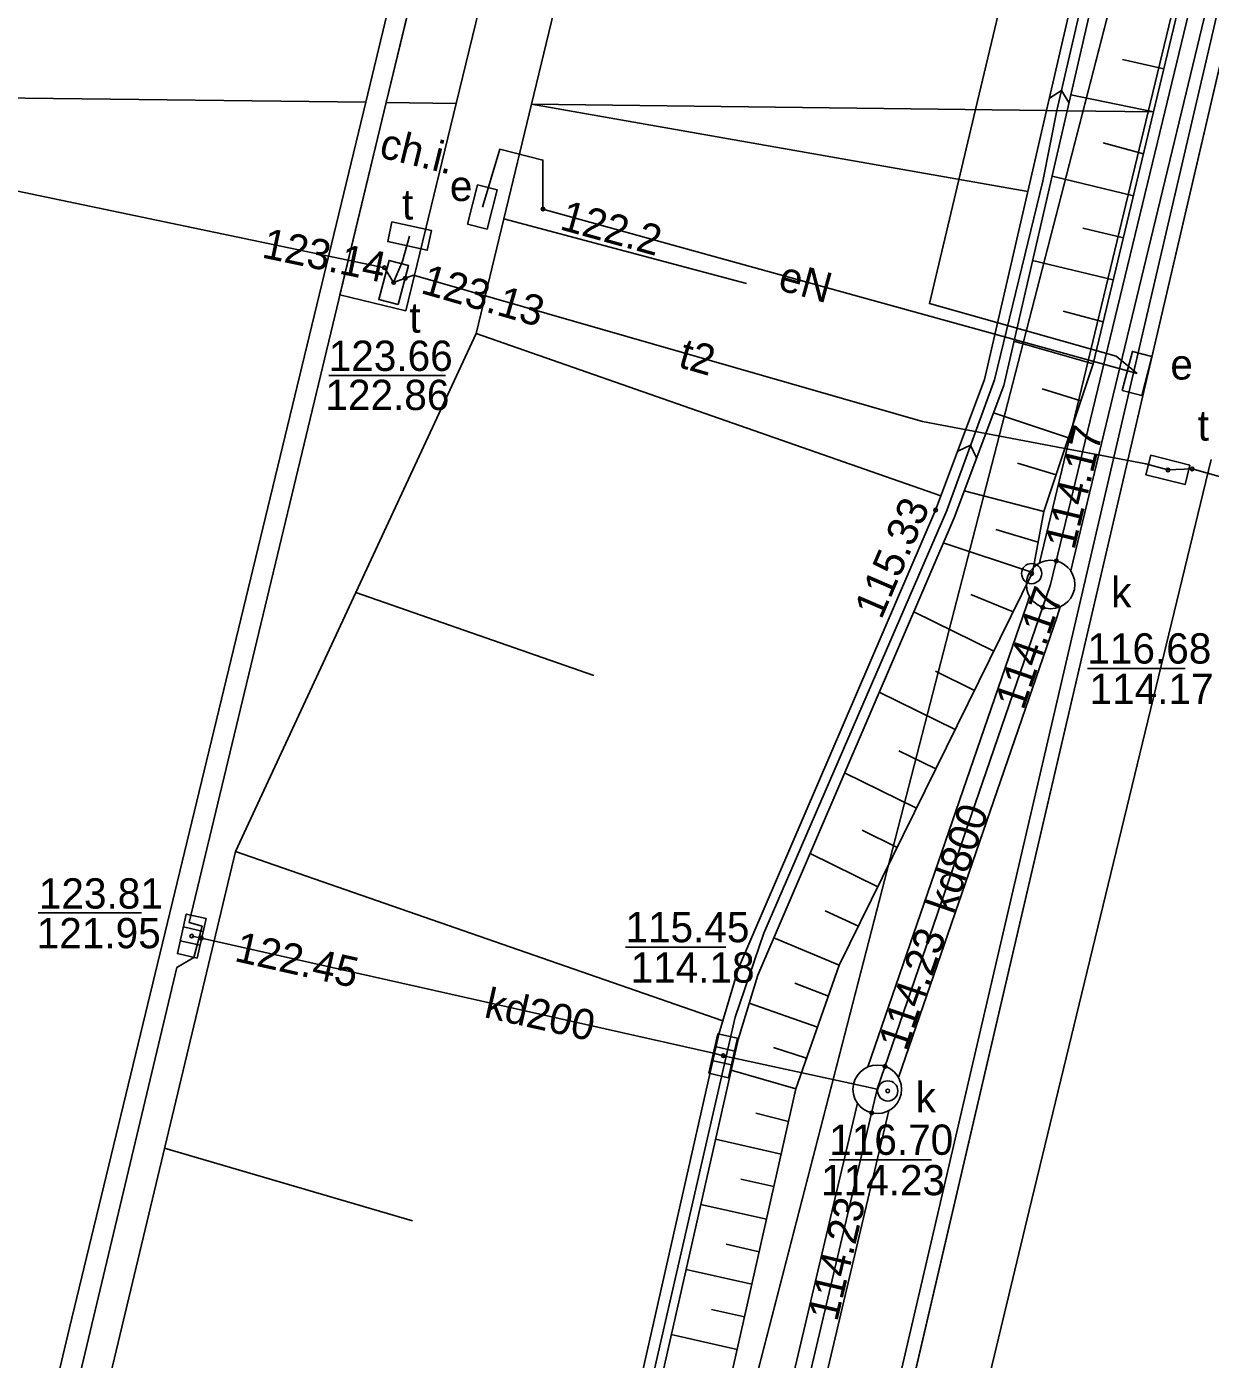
# Model space of a CAD drawing. Extents: x 6424617 to 6425697, y 5665845 to 5667190.
# Drawn here: x 6425313.55 to 6425342.83, y 5666283.39 to 5666316.36 of the extents above; entities that cross this region are included whole.
import ezdxf

# ---------------------------------------------------------------- set-up
doc = ezdxf.new("R2010")
doc.units = 0
for name, color, linetype in [('Warstwa 1', 7, 'Continuous'), ('Warstwa 12', 7, 'Continuous'), ('Warstwa 13', 7, 'Continuous'), ('Warstwa 14', 7, 'Continuous'), ('Warstwa 15', 7, 'Continuous'), ('Warstwa 16', 7, 'Continuous'), ('Warstwa 2', 7, 'Continuous'), ('Warstwa 20', 7, 'Continuous'), ('Warstwa 21', 7, 'Continuous'), ('Warstwa 25', 7, 'Continuous'), ('Warstwa 4', 7, 'Continuous'), ('Warstwa 5', 7, 'Continuous'), ('Warstwa 6', 7, 'Continuous'), ('Warstwa 61', 7, 'Continuous'), ('Warstwa 8', 7, 'Continuous'), ('Warstwa 9', 7, 'Continuous')]:
    doc.layers.add(name, color=color, linetype=linetype)

msp = doc.modelspace()

# ---------------------------------------------------------------- linework, layer by layer
at = {"layer": 'Warstwa 1'}
for p, q in [((6425328.388, 5666270.5), (6425353.441, 5666367.596)), ((6425328.388, 5666270.5), (6425353.441, 5666367.596)), ((6425325.89, 5666241.74), (6425352.06, 5666353.98)), ((6425325.89, 5666241.74), (6425352.06, 5666353.98))]:
    msp.add_line(p, q, dxfattribs=at)
at = {"layer": 'Warstwa 12'}
for points in [[(6425398.761, 5666563.583), (6425397.55, 5666559.5), (6425397.03, 5666557.16), (6425392.45, 5666536.96), (6425386, 5666508.09), (6425382.01, 5666490.27), (6425381.21, 5666479.99), (6425379.9, 5666475.3), (6425381.52, 5666474.89), (6425375.93, 5666454.14), (6425373.99, 5666454.38), (6425373.44, 5666451.82), (6425375.23, 5666451.4), (6425362.43, 5666401.17), (6425355.8, 5666402.66), (6425355.08, 5666402.04), (6425351.66, 5666389.66), (6425350.42, 5666384.46), (6425347.89, 5666373.29), (6425344.69, 5666359.22), (6425346.02, 5666355.28), (6425340.77, 5666330.04), (6425337.023, 5666314.31)], [(6425341.293, 5666314.258), (6425351.556, 5666356.819)], [(6425352.334, 5666356.631), (6425342.114, 5666314.249)], [(6425337.023, 5666314.31), (6425335.88, 5666309.51), (6425340.5, 5666308.21), (6425341.02, 5666307.78)], [(6425338.604, 5666303.093), (6425341.293, 5666314.258)], [(6425342.114, 5666314.249), (6425339.438, 5666303.145), (6425339.376, 5666302.897)], [(6425358.838, 5666300.979), (6425358.436, 5666301.076), (6425355.839, 5666301.623), (6425342.381, 5666305.421), (6425341.781, 5666305.394), (6425341.237, 5666305.542), (6425335.71, 5666306.592), (6425323.113, 5666310.211), (6425322.626, 5666310.032), (6425322.397, 5666310.399), (6425305.47, 5666313.931)], [(6425341.02, 5666307.78), (6425326.32, 5666311.85), (6425326.32, 5666313.06), (6425325.25, 5666313.33), (6425324.82, 5666311.9)], [(6425322.626, 5666310.032), (6425322.848, 5666310.561), (6425323.02, 5666311.182)], [(6425334.359, 5666290.624), (6425334.442, 5666290.861), (6425338.281, 5666302.028), (6425338.359, 5666302.262)], [(6425339.118, 5666302.009), (6425339.039, 5666301.772), (6425335.116, 5666290.359)], [(6425334.59, 5666290.07), (6425333.91, 5666290.22), (6425331.02, 5666290.85), (6425330.78, 5666290.9), (6425330.54, 5666290.96), (6425317.87, 5666293.81), (6425317.63, 5666293.86)], [(6425320.019, 5666230.08), (6425320.081, 5666230.334), (6425334.098, 5666289.726)], [(6425334.876, 5666289.542), (6425320.859, 5666230.146), (6425320.795, 5666229.889)]]:
    msp.add_lwpolyline(points, dxfattribs=at)
at = {"layer": 'Warstwa 14'}
for p, q in [((6425323.909, 5666307.735), (6425321.022, 5666307.735)), ((6425339.79, 5666300.478), (6425342.208, 5666300.478)), ((6425316.386, 5666294.435), (6425313.829, 5666294.435)), ((6425330.843, 5666293.585), (6425328.364, 5666293.585)), ((6425333.4, 5666288.323), (6425335.936, 5666288.323))]:
    msp.add_line(p, q, dxfattribs=at)
for centre in [(6425326.32, 5666311.85), (6425322.397, 5666310.399), (6425322.627, 5666310.032), (6425322.913, 5666310.138), (6425341.781, 5666305.394), (6425342.381, 5666305.421), (6425339.021, 5666303.143), (6425338.41, 5666302.83), (6425338.685, 5666301.993), (6425317.63, 5666293.86), (6425317.87, 5666293.81), (6425330.78, 5666290.9), (6425334.785, 5666290.637), (6425334.85, 5666290.03), (6425334.452, 5666289.486)]:
    msp.add_circle(centre, 0.045, dxfattribs=at)
at = {"layer": 'Warstwa 16'}
for centre in [(6425338.88, 5666302.56), (6425334.59, 5666290.07)]:
    msp.add_circle(centre, 0.6, dxfattribs=at)
at = {"layer": 'Warstwa 2'}
for points in [[(6425342.431, 5666314.245), (6425342.9, 5666316.26), (6425351.432, 5666353.898), (6425342.677, 5666355.997), (6425354.705, 5666404.396), (6425364.488, 5666402.728), (6425382.828, 5666478.302), (6425401.605, 5666563.549)], [(6425303.473, 5666148.344), (6425306.362, 5666159.088), (6425314.292, 5666194.437), (6425325.907, 5666243.233), (6425342.431, 5666314.245)]]:
    msp.add_lwpolyline(points, dxfattribs=at)
at = {"layer": 'Warstwa 20'}
for points in [[(6425326.04, 5666314.442), (6425336.507, 5666357.769), (6425337.041, 5666371.794), (6425341.788, 5666390.934), (6425346.79, 5666410.35), (6425362.358, 5666467.618), (6425366.796, 5666476.821), (6425368.004, 5666481.671), (6425368.42, 5666492.007), (6425372.53, 5666509.068), (6425385.231, 5666561.556), (6425385.761, 5666563.74)], [(6425357.772, 5666382.553), (6425355.492, 5666383.194), (6425351.527, 5666369.131), (6425351.075, 5666355.185), (6425350.421, 5666351.646), (6425344.982, 5666329.077), (6425341.427, 5666314.257)], [(6425304.533, 5666236.23), (6425305.726, 5666241.337), (6425307.517, 5666249.107), (6425311.684, 5666266.587), (6425318.716, 5666295.95), (6425324.669, 5666308.767), (6425326.04, 5666314.442)], [(6425303.561, 5666155.601), (6425305.779, 5666165.581), (6425308.459, 5666179.937), (6425311.226, 5666193.042), (6425314.843, 5666210.522), (6425317.953, 5666224.34), (6425319.999, 5666234.617), (6425323.075, 5666247.035), (6425326.767, 5666264.304), (6425332.574, 5666290.078), (6425333.65, 5666293.139), (6425338.427, 5666302.856), (6425338.714, 5666304.362), (6425339.931, 5666308.021), (6425341.427, 5666314.257)]]:
    msp.add_lwpolyline(points, dxfattribs=at)
at = {"layer": 'Warstwa 21'}
for points in [[(6425338.781, 5666314.289), (6425342.093, 5666328.629), (6425347.916, 5666354.162), (6425348.109, 5666355.419), (6425348.432, 5666366.657), (6425348.554, 5666369.545), (6425350.265, 5666377.317), (6425350.911, 5666379.876), (6425351.627, 5666381.874), (6425353.464, 5666386.247), (6425353.858, 5666388.451), (6425354.565, 5666392.214), (6425355.215, 5666394.983), (6425357.587, 5666405.034), (6425362.218, 5666424.397), (6425369.236, 5666451.879), (6425372.67, 5666465.301), (6425376.112, 5666474.212), (6425378.491, 5666484.102), (6425377.911, 5666489.644), (6425387.002, 5666528.883), (6425394.525, 5666561.078), (6425395.128, 5666563.627)], [(6425339.288, 5666314.283), (6425342.571, 5666328.52), (6425348.415, 5666354.073), (6425348.608, 5666355.37), (6425348.932, 5666366.648), (6425349.053, 5666369.496), (6425350.743, 5666377.208), (6425351.388, 5666379.727), (6425352.084, 5666381.686), (6425353.882, 5666385.964), (6425359.308, 5666384.556)], [(6425303.709, 5666167.856), (6425306.281, 5666180.067), (6425309.082, 5666193.42), (6425312.692, 5666210.531), (6425315.747, 5666224.59), (6425320.772, 5666247.497), (6425324.765, 5666265.311), (6425330.668, 5666291.433), (6425331.158, 5666293.064), (6425336.034, 5666304.4), (6425337.243, 5666307.629), (6425338.781, 5666314.289)], [(6425303.853, 5666165.956), (6425304.142, 5666167.441), (6425306.779, 5666179.958), (6425309.581, 5666193.311), (6425313.191, 5666210.422), (6425316.245, 5666224.481), (6425321.26, 5666247.388), (6425325.243, 5666265.202), (6425331.146, 5666291.304), (6425331.635, 5666292.896), (6425336.491, 5666304.212), (6425337.72, 5666307.481), (6425339.288, 5666314.283)], [(6425324.453, 5666311.478), (6425324.703, 5666312.447), (6425325.187, 5666312.322), (6425324.937, 5666311.353), (6425324.453, 5666311.478)], [(6425340.653, 5666307.358), (6425340.903, 5666308.327), (6425341.387, 5666308.202), (6425341.137, 5666307.233), (6425340.653, 5666307.358)]]:
    msp.add_lwpolyline(points, dxfattribs=at)
at = {"layer": 'Warstwa 25'}
msp.add_circle((6425336.034, 5666304.4), 0.045, dxfattribs=at)
at = {"layer": 'Warstwa 4'}
for p, q in [((6425317.912, 5666293.976), (6425317.425, 5666294.086)), ((6425317.835, 5666293.634), (6425317.348, 5666293.744)), ((6425331.063, 5666291.014), (6425330.576, 5666291.127)), ((6425330.984, 5666290.673), (6425330.497, 5666290.786))]:
    msp.add_line(p, q, dxfattribs=at)
msp.add_lwpolyline([(6425322.584, 5666311.532), (6425323.562, 5666311.32), (6425323.456, 5666310.832), (6425322.478, 5666311.044), (6425322.584, 5666311.532)], dxfattribs=at)
for points in [[(6425322.741, 5666309.485), (6425322.996, 5666310.452), (6425322.513, 5666310.579), (6425322.258, 5666309.612)], [(6425342.327, 5666305.515), (6425341.356, 5666305.758), (6425341.235, 5666305.273), (6425342.206, 5666305.03)], [(6425317.984, 5666294.293), (6425317.764, 5666293.317), (6425317.276, 5666293.427), (6425317.496, 5666294.403)], [(6425331.136, 5666291.331), (6425330.911, 5666290.357), (6425330.424, 5666290.469), (6425330.649, 5666291.443)]]:
    msp.add_lwpolyline(points, close=True, dxfattribs=at)
for centre in [(6425338.41, 5666302.83), (6425334.85, 5666290.03)]:
    msp.add_circle(centre, 0.25, dxfattribs=at)
at = {"layer": 'Warstwa 6'}
for points in [[(6425305.245, 5666173.41), (6425312.278, 5666201.804), (6425314.518, 5666211.716), (6425317.57, 5666225.189), (6425322.489, 5666245.769), (6425323.828, 5666251.474), (6425324.47, 5666254.176), (6425328.388, 5666270.5), (6425353.441, 5666367.596), (6425363.818, 5666408.694)], [(6425363.818, 5666408.694), (6425353.441, 5666367.596), (6425328.388, 5666270.5), (6425324.47, 5666254.176), (6425323.828, 5666251.474), (6425322.489, 5666245.769), (6425317.57, 5666225.189), (6425314.518, 5666211.716), (6425312.278, 5666201.804), (6425305.245, 5666173.41)], [(6425306.64, 5666159.22), (6425325.89, 5666241.74), (6425352.06, 5666353.98), (6425364.93, 5666402.71)], [(6425364.93, 5666402.71), (6425352.06, 5666353.98), (6425325.89, 5666241.74), (6425306.64, 5666159.22)], [(6425322.442, 5666314.486), (6425324.302, 5666322.218), (6425324.706, 5666322.46), (6425324.921, 5666323.247), (6425324.592, 5666323.333), (6425324.776, 5666324.11), (6425324.288, 5666324.229)], [(6425304.565, 5666238.913), (6425304.749, 5666239.038), (6425304.958, 5666239.78), (6425304.599, 5666239.877), (6425310.762, 5666265.954), (6425311.177, 5666266.196), (6425311.391, 5666266.973), (6425311.062, 5666267.069), (6425317.264, 5666293.085), (6425317.678, 5666293.328), (6425317.892, 5666294.104), (6425317.564, 5666294.2), (6425322.442, 5666314.486)]]:
    msp.add_lwpolyline(points, dxfattribs=at)
at = {"layer": 'Warstwa 61'}
for points in [[(6425341.704, 5666314.254), (6425342.827, 5666318.91), (6425348.934, 5666344.24), (6425352.05, 5666357.16), (6425353.95, 5666371.17), (6425355.78, 5666379.24), (6425357.362, 5666385.334)], [(6425341.704, 5666314.254), (6425338.88, 5666302.56), (6425334.59, 5666290.07), (6425328.175, 5666262.886), (6425321.743, 5666235.634), (6425320.3, 5666229.55), (6425315.738, 5666208.383), (6425309.864, 5666181.13), (6425306.96, 5666167.67), (6425303.535, 5666153.405)]]:
    msp.add_lwpolyline(points, dxfattribs=at)
at = {"layer": 'Warstwa 8'}
for p, q in [((6425321.934, 5666314.492), (6425324.288, 5666324.229)), ((6425307.571, 5666314.665), (6425321.934, 5666314.492)), ((6425307.571, 5666314.665), (6425321.934, 5666314.492)), ((6425314.602, 5666284.17), (6425321.934, 5666314.492)), ((6425338.35, 5666287.07), (6425342.85, 5666305.65)), ((6425333.94, 5666268.74), (6425338.35, 5666287.07)), ((6425304.603, 5666242.063), (6425314.602, 5666284.17))]:
    msp.add_line(p, q, dxfattribs=at)
at = {"layer": 'Warstwa 9'}
for p, q in [((6425339.035, 5666314.286), (6425342.607, 5666329.866)), ((6425324.173, 5666314.465), (6425326.766, 5666325.174)), ((6425322.442, 5666314.486), (6425324.302, 5666322.218)), ((6425341.681, 5666315.316), (6425340.657, 5666315.552)), ((6425338.852, 5666314.594), (6425339.148, 5666314.78)), ((6425339.334, 5666314.483), (6425339.148, 5666314.78)), ((6425341.427, 5666314.257), (6425339.378, 5666314.675)), ((6425321.298, 5666309.727), (6425322.442, 5666314.486)), ((6425322.442, 5666314.486), (6425324.173, 5666314.465)), ((6425322.442, 5666314.486), (6425324.173, 5666314.465)), ((6425322.929, 5666309.328), (6425324.173, 5666314.465)), ((6425326.04, 5666314.442), (6425338.318, 5666312.285)), ((6425338.686, 5666312.539), (6425339.035, 5666314.286)), ((6425341.178, 5666313.218), (6425340.176, 5666313.491)), ((6425337.493, 5666307.626), (6425338.686, 5666312.539)), ((6425340.928, 5666312.178), (6425338.914, 5666312.662)), ((6425325.354, 5666311.604), (6425331.353, 5666310.009)), ((6425340.679, 5666311.139), (6425339.676, 5666311.38)), ((6425340.43, 5666310.1), (6425338.434, 5666310.579)), ((6425321.298, 5666309.727), (6425322.929, 5666309.328)), ((6425340.18, 5666309.06), (6425339.192, 5666309.32)), ((6425324.669, 5666308.767), (6425336.167, 5666304.756)), ((6425339.931, 5666308.021), (6425337.973, 5666308.581)), ((6425336.311, 5666304.394), (6425337.493, 5666307.626)), ((6425339.626, 5666307.106), (6425338.673, 5666307.401)), ((6425339.322, 5666306.192), (6425337.467, 5666306.809)), ((6425336.58, 5666305.858), (6425336.901, 5666306.007)), ((6425337.047, 5666305.692), (6425336.901, 5666306.007)), ((6425339.018, 5666305.277), (6425338.061, 5666305.56)), ((6425338.714, 5666304.362), (6425336.741, 5666304.877)), ((6425331.785, 5666293.936), (6425336.311, 5666304.394)), ((6425338.57, 5666303.609), (6425337.527, 5666303.922)), ((6425338.427, 5666302.856), (6425336.225, 5666303.592)), ((6425321.692, 5666302.358), (6425327.579, 5666300.308)), ((6425337.95, 5666301.884), (6425336.904, 5666302.312)), ((6425337.472, 5666300.913), (6425335.493, 5666301.887)), ((6425336.994, 5666299.941), (6425336.03, 5666300.416)), ((6425336.516, 5666298.969), (6425334.638, 5666299.893)), ((6425336.038, 5666297.998), (6425335.124, 5666298.447)), ((6425335.561, 5666297.026), (6425333.783, 5666297.901)), ((6425335.083, 5666296.054), (6425334.219, 5666296.479)), ((6425318.716, 5666295.95), (6425330.766, 5666291.76)), ((6425334.605, 5666295.082), (6425332.927, 5666295.907)), ((6425334.128, 5666294.11), (6425333.303, 5666294.487)), ((6425331.071, 5666291.856), (6425331.785, 5666293.936)), ((6425333.65, 5666293.139), (6425332.031, 5666293.819)), ((6425333.381, 5666292.374), (6425332.554, 5666292.693)), ((6425333.112, 5666291.608), (6425331.422, 5666292.204)), ((6425328.093, 5666278.84), (6425331.071, 5666291.856)), ((6425332.843, 5666290.843), (6425332.02, 5666291.107)), ((6425332.574, 5666290.078), (6425330.973, 5666290.539)), ((6425332.392, 5666289.272), (6425331.586, 5666289.479)), ((6425332.211, 5666288.467), (6425330.587, 5666288.833)), ((6425316.958, 5666288.609), (6425323.094, 5666286.814)), ((6425332.03, 5666287.661), (6425331.217, 5666287.844)), ((6425331.848, 5666286.856), (6425330.223, 5666287.222)), ((6425331.666, 5666286.05), (6425330.854, 5666286.234)), ((6425331.485, 5666285.245), (6425329.859, 5666285.612)), ((6425331.304, 5666284.44), (6425330.49, 5666284.623)), ((6425331.122, 5666283.634), (6425329.494, 5666284.001))]:
    msp.add_line(p, q, dxfattribs=at)
for points in [[(6425341.788, 5666390.934), (6425337.041, 5666371.794), (6425336.507, 5666357.769), (6425326.04, 5666314.442), (6425338.781, 5666314.289), (6425342.093, 5666328.629), (6425347.916, 5666354.162), (6425348.109, 5666355.419), (6425348.432, 5666366.657), (6425348.554, 5666369.545), (6425350.265, 5666377.317), (6425350.911, 5666379.876), (6425351.627, 5666381.874), (6425353.464, 5666386.247), (6425353.858, 5666388.451)], [(6425309.581, 5666193.311), (6425313.191, 5666210.422), (6425316.245, 5666224.481), (6425321.26, 5666247.388), (6425325.243, 5666265.202), (6425331.146, 5666291.304), (6425331.635, 5666292.896), (6425336.491, 5666304.212), (6425337.72, 5666307.481), (6425339.288, 5666314.283), (6425338.781, 5666314.289), (6425337.243, 5666307.629), (6425336.034, 5666304.4), (6425331.158, 5666293.064), (6425330.668, 5666291.433), (6425324.765, 5666265.311), (6425320.772, 5666247.497), (6425315.747, 5666224.59), (6425312.692, 5666210.531), (6425309.082, 5666193.42)], [(6425311.226, 5666193.042), (6425314.843, 5666210.522), (6425317.953, 5666224.34), (6425319.999, 5666234.617), (6425323.075, 5666247.035), (6425326.767, 5666264.304), (6425332.574, 5666290.078), (6425333.65, 5666293.139), (6425338.427, 5666302.856), (6425338.714, 5666304.362), (6425339.931, 5666308.021), (6425341.427, 5666314.257), (6425339.288, 5666314.283), (6425337.72, 5666307.481), (6425336.491, 5666304.212), (6425331.635, 5666292.896), (6425331.146, 5666291.304), (6425325.243, 5666265.202), (6425321.26, 5666247.388), (6425316.245, 5666224.481), (6425313.191, 5666210.422), (6425309.581, 5666193.311)]]:
    msp.add_lwpolyline(points, dxfattribs=at)
for points in [[(6425338.781, 5666314.289), (6425342.093, 5666328.629), (6425347.916, 5666354.162), (6425348.109, 5666355.419), (6425348.432, 5666366.657), (6425348.554, 5666369.545), (6425350.265, 5666377.317), (6425350.911, 5666379.876), (6425351.627, 5666381.874), (6425353.464, 5666386.247), (6425353.951, 5666386.129), (6425352.084, 5666381.686), (6425351.388, 5666379.727), (6425350.743, 5666377.208), (6425349.053, 5666369.496), (6425348.932, 5666366.648), (6425348.608, 5666355.37), (6425348.415, 5666354.073), (6425342.571, 5666328.52), (6425339.288, 5666314.283)], [(6425357.772, 5666382.553), (6425355.492, 5666383.194), (6425351.527, 5666369.131), (6425351.075, 5666355.185), (6425350.421, 5666351.646), (6425344.982, 5666329.077), (6425341.427, 5666314.257), (6425339.288, 5666314.283), (6425342.571, 5666328.52), (6425348.415, 5666354.073), (6425348.608, 5666355.37), (6425348.932, 5666366.648), (6425349.053, 5666369.496), (6425350.743, 5666377.208), (6425351.388, 5666379.727), (6425352.084, 5666381.686), (6425353.882, 5666385.964), (6425359.308, 5666384.556)], [(6425303.709, 5666167.856), (6425306.281, 5666180.067), (6425309.082, 5666193.42), (6425312.692, 5666210.531), (6425315.747, 5666224.59), (6425320.772, 5666247.497), (6425324.765, 5666265.311), (6425330.668, 5666291.433), (6425331.158, 5666293.064), (6425336.034, 5666304.4), (6425337.243, 5666307.629), (6425338.781, 5666314.289), (6425326.04, 5666314.442), (6425324.669, 5666308.767), (6425318.716, 5666295.95), (6425311.684, 5666266.587), (6425307.517, 5666249.107), (6425305.726, 5666241.337), (6425304.533, 5666236.23)]]:
    msp.add_lwpolyline(points, close=True, dxfattribs=at)

# ---------------------------------------------------------------- texts
at = {"layer": 'Warstwa 13'}
for s, rotation, p in [('eN', 344.5253, (6425332.103, 5666309.86)), ('t2', 343.9695, (6425329.638, 5666307.947)), ('kd800', 71.0296, (6425336.47, 5666294.376)), ('kd200', 347.3213, (6425324.837, 5666291.859))]:
    msp.add_text(s, height=0.75, rotation=rotation, dxfattribs=at).set_placement(p)
at = {"layer": 'Warstwa 14'}
for s, rotation, p in [('122.2', 344.5253, (6425326.706, 5666311.354)), ('123.14', 348.2151, (6425319.339, 5666310.654)), ('123.13', 343.9695, (6425323.267, 5666309.777)), ('114.17', 76.4498, (6425339.465, 5666303.393)), ('114.17', 71.0296, (6425338.206, 5666299.426)), ('122.45', 347.3213, (6425318.661, 5666293.248)), ('114.23', 71.0296, (6425335.306, 5666290.988)), ('114.23', 76.7248, (6425333.598, 5666284.3))]:
    msp.add_text(s, height=0.75, rotation=rotation, dxfattribs=at).set_placement(p)
for s, p in [('122.86', (6425320.937, 5666306.876)), ('114.17', (6425339.843, 5666299.603)), ('121.95', (6425313.795, 5666293.559)), ('114.18', (6425328.488, 5666292.709)), ('114.23', (6425333.2, 5666287.448))]:
    msp.add_text(s, height=0.75, dxfattribs=at).set_placement(p)
at = {"layer": 'Warstwa 15'}
for s, p in [('123.66', (6425321.019, 5666307.844)), ('116.68', (6425339.788, 5666300.603)), ('123.81', (6425313.848, 5666294.541)), ('115.45', (6425328.361, 5666293.708)), ('116.70', (6425333.402, 5666288.448))]:
    msp.add_text(s, height=0.75, dxfattribs=at).set_placement(p)
at = {"layer": 'Warstwa 21'}
for p in [(6425324.016, 5666312.048), (6425341.842, 5666307.63)]:
    msp.add_text('e', height=0.75, dxfattribs=at).set_placement(p)
at = {"layer": 'Warstwa 25'}
msp.add_text('115.33', height=0.75, rotation=66.7267, dxfattribs=at).set_placement((6425334.69, 5666301.671))
at = {"layer": 'Warstwa 4'}
msp.add_text('t', height=0.75, dxfattribs=at).set_placement((6425322.834, 5666311.59))
at = {"layer": 'Warstwa 5'}
for s, p in [('t', (6425323.015, 5666308.79)), ('t', (6425342.517, 5666306.119)), ('k', (6425340.378, 5666301.993)), ('k', (6425335.539, 5666289.501))]:
    msp.add_text(s, height=0.75, dxfattribs=at).set_placement(p)
at = {"layer": 'Warstwa 9'}
msp.add_text('ch.i.', height=0.75, rotation=346.2441, dxfattribs=at).set_placement((6425322.239, 5666313.138))

doc.saveas('drawing.dxf')
